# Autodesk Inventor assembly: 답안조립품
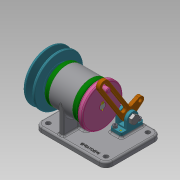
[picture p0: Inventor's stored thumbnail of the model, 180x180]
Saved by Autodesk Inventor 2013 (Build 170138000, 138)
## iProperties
Created: 2019-09
Part Number: 답안조립품
Document SubType Name: Assembly
Designer: Administrator
Author: Administrator
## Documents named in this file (19)
- C:\Users\Administrator\Downloads\390904V1011\답안조립품.iam
- C:\Users\Administrator\Downloads\390904V1011\본체.ipt
- C:\Users\Administrator\Downloads\390904V1011\V-벨트풀리.ipt
- C:\Users\Administrator\Downloads\390904V1011\너트 M8.ipt
- C:\Users\Administrator\Downloads\390904V1011\너트 M10x1.ipt
- C:\Users\Administrator\Downloads\390904V1011\돌림판.ipt
- C:\Users\Administrator\Downloads\390904V1011\멈춤나사 M3x5.ipt
- C:\Users\Administrator\Downloads\390904V1011\베어링 6004.ipt
- C:\Users\Administrator\Downloads\390904V1011\볼트 M4.ipt
- C:\Users\Administrator\Downloads\390904V1011\오일 실 17 30 5.ipt
- C:\Users\Administrator\Downloads\390904V1011\와셔 8x15.5.ipt
- C:\Users\Administrator\Downloads\390904V1011\축.ipt
- C:\Users\Administrator\Downloads\390904V1011\커버.ipt
- C:\Users\Administrator\Downloads\390904V1011\크랭크.ipt
- C:\Users\Administrator\Downloads\390904V1011\키 4 x 4 x 8.ipt
- C:\Users\Administrator\Downloads\390904V1011\키 5 x 5 x 12.ipt
- C:\Users\Administrator\Downloads\390904V1011\핀 3 x 8.ipt
- C:\Users\Administrator\Downloads\390904V1011\힌지 축.ipt
- C:\Users\Administrator\Downloads\390904V1011\힌지.ipt
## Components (3 placed, 2 different names)
1. V-벨트풀리:1
2. 핀 3 x 8:1 — 플러쉬:2
3. 핀 3 x 8:2 — 플러쉬:3
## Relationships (2: Flush 2)
- 플러쉬:2 [Flush]: 핀 3 x 8:1
- 플러쉬:3 [Flush]: 핀 3 x 8:2
